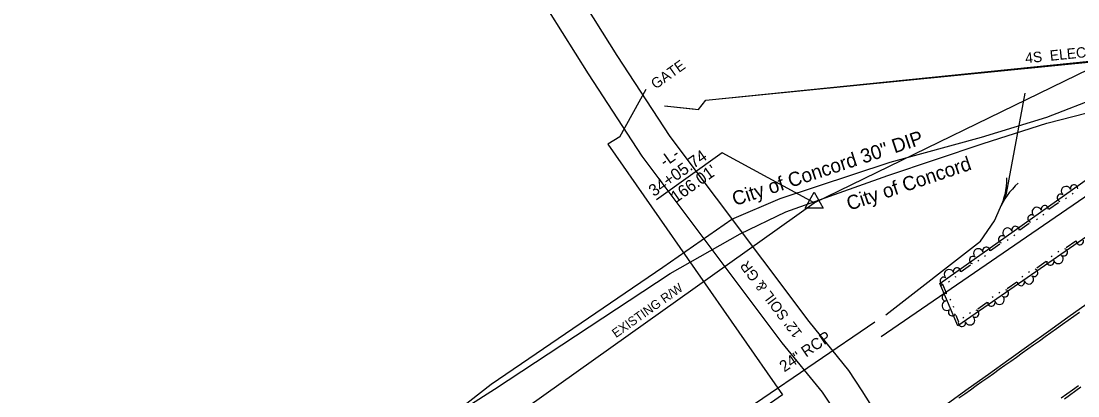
# Model space of a CAD drawing. Extents: x 1577032 to 1581865, y 611492 to 615011.
# Drawn here: x 1579793.8 to 1580168.3, y 613586.8 to 613719.5 of the extents above; entities that cross this region are included whole.
import ezdxf

# ---------------------------------------------------------------- set-up
doc = ezdxf.new("R2010")
doc.units = 0
for name, color, linetype in [('Exist Hydro Jurisdictional Stream or Body of Water', 7, 'Continuous'), ('Exist Hydro Stream Flow Arrow CELL', 7, 'Continuous'), ('Exist Other Culture Fence Line', 7, 'Continuous'), ('Exist Other Culture Fence Line Leader', 7, 'Continuous'), ('Exist Right of Way Line', 7, 'Continuous'), ('Exist Right of Way Line Text', 7, 'Continuous'), ('Exist Right of Way Monument CELL', 7, 'Continuous'), ('Exist Right of Way Monument Leader', 7, 'Continuous'), ('Exist Right of Way Monument Text', 7, 'Continuous'), ('Exist Roads EOP', 7, 'Continuous'), ('Exist Roads EOT', 7, 'Continuous'), ('Exist Structure Minor Pipes RCP 24 Inch', 7, 'Continuous'), ('Exist Structure Minor Pipes RCP 24 Inch Text', 7, 'Continuous'), ('Exist Utilities Telephone UG FO SUE LOS B', 7, 'Continuous'), ('Exist Utilities Telephone UG FO SUE LOS B Text', 7, 'Continuous'), ('Exist Utilities Water UG Line SUE LOS B', 7, 'Continuous'), ('Exist Utilities Water UG Line SUE LOS B Text', 7, 'Continuous'), ('Old_Level_11', 7, 'Continuous'), ('Old_Level_8', 7, 'Continuous'), ('Scratch_Level_4', 7, 'Continuous'), ('Scratch_Level_6', 7, 'Continuous')]:
    doc.layers.add(name, color=color, linetype=linetype)

msp = doc.modelspace()

# ---------------------------------------------------------------- linework, layer by layer
at = {"layer": 'Exist Hydro Jurisdictional Stream or Body of Water'}
msp.add_lwpolyline([(1580100.25, 613615.55), (1580133.87, 613641.64), (1580138.78, 613648.8), (1580143.1, 613658.51), (1580149.63, 613693.95)], dxfattribs=at)
at = {"layer": 'Exist Hydro Stream Flow Arrow CELL'}
msp.add_line((1580143.1, 613658.51), (1580143.1, 613658.51), dxfattribs=at)
for points in [[(1580143.06, 613664.01), (1580143.06, 613662.54), (1580142.9, 613661.05), (1580142.72, 613659.58), (1580142.43, 613658.17), (1580142.04, 613656.73), (1580141.58, 613655.31), (1580141.05, 613653.95)], [(1580147.23, 613662.13), (1580146.14, 613661.16), (1580145.13, 613660.05), (1580144.16, 613658.94), (1580143.29, 613657.78), (1580142.48, 613656.54), (1580141.72, 613655.25), (1580141.05, 613653.95)]]:
    msp.add_lwpolyline(points, dxfattribs=at)
at = {"layer": 'Exist Other Culture Fence Line'}
for p in [(1580036.43, 613691.58), (1580098.64, 613607.82)]:
    msp.add_line(p, (1580251.9, 613712.92), dxfattribs=at)
msp.add_lwpolyline([(1580021.78, 613689.53), (1580031.98, 613688.46)], dxfattribs=at)
at = {"layer": 'Exist Right of Way Line'}
for p, q in [((1580074.87, 613655.16), (1580329.14, 613778.75)), ((1579178.76, 613018.8), (1580074.87, 613655.16))]:
    msp.add_line(p, q, dxfattribs=at)
at = {"layer": 'Exist Right of Way Monument CELL'}
msp.add_line((1580074.87, 613655.16), (1580074.87, 613655.16), dxfattribs=at)
msp.add_lwpolyline([(1580071.63, 613653.27), (1580074.88, 613658.91), (1580078.12, 613653.27)], close=True, dxfattribs=at)
at = {"layer": 'Exist Right of Way Monument Leader'}
msp.add_lwpolyline([(1580074.87, 613655.16), (1580042.24, 613672.89), (1580018.97, 613656.24)], dxfattribs=at)
at = {"layer": 'Exist Roads EOP'}
for points in [[(1580171.59, 613619.36), (1580164.85, 613614.58), (1580157.96, 613609.65), (1580150.94, 613604.62), (1580143.84, 613599.55), (1580136.66, 613594.43), (1580129.41, 613589.25), (1580122.09, 613584.03)], [(1580163.65, 613585.82), (1580169.43, 613589.97)]]:
    msp.add_lwpolyline(points, dxfattribs=at)
at = {"layer": 'Exist Roads EOT'}
for points in [[(1580168.96, 613616.38), (1580166.92, 613614.93), (1580164.89, 613613.48), (1580162.85, 613612.04), (1580160.81, 613610.59), (1580158.78, 613609.14), (1580156.74, 613607.69), (1580154.71, 613606.24), (1580152.67, 613604.79), (1580150.63, 613603.35), (1580148.6, 613601.9), (1580146.56, 613600.45), (1580144.53, 613599), (1580142.49, 613597.55), (1580140.46, 613596.11), (1580138.42, 613594.66), (1580136.38, 613593.21), (1580134.35, 613591.76), (1580132.31, 613590.31), (1580130.28, 613588.86), (1580128.24, 613587.42), (1580126.21, 613585.97)], [(1580162.43, 613586.11), (1580164.46, 613587.56), (1580166.5, 613589), (1580168.54, 613590.45)]]:
    msp.add_lwpolyline(points, dxfattribs=at)
at = {"layer": 'Exist Structure Minor Pipes RCP 24 Inch'}
msp.add_line((1580054.05, 613584.23), (1580096.34, 613613.07), dxfattribs=at)
at = {"layer": 'Exist Utilities Telephone UG FO SUE LOS B'}
msp.add_lwpolyline([(1579762.43, 613445.5), (1579805.52, 613477.49), (1579874.3, 613528.42), (1579927.63, 613567.61), (1579961.57, 613589.13), (1580023.79, 613630.1), (1580048.6, 613644.24), (1580064.79, 613652.02), (1580101.01, 613664.86), (1580134.79, 613676.2), (1580157.3, 613683.34), (1580171.65, 613687.07), (1580205.63, 613699.27), (1580257.8, 613718.78), (1580277.93, 613732.3), (1580322.48, 613762.42), (1580357.71, 613789.14), (1580371.84, 613797.02), (1580398.85, 613808.57), (1580440.4, 613836.96), (1580497.32, 613877.42), (1580541.92, 613911.34), (1580565.99, 613928.5)], dxfattribs=at)
at = {"layer": 'Exist Utilities Water UG Line SUE LOS B'}
for p, q in [((1580157.33, 613685.56), (1580179.53, 613694.09)), ((1580134.18, 613678.38), (1580157.33, 613685.56)), ((1580101.85, 613669.53), (1580134.18, 613678.38)), ((1580062.81, 613656.66), (1580101.85, 613669.53)), ((1580045.74, 613649.33), (1580062.81, 613656.66)), ((1580021.22, 613632.44), (1580045.74, 613649.33)), ((1579960.34, 613590.95), (1580021.22, 613632.44)), ((1579928.88, 613566.57), (1579960.34, 613590.95))]:
    msp.add_line(p, q, dxfattribs=at)
at = {"layer": 'Old_Level_11'}
for points in [[(1580196.05, 613660.28), (1580125.81, 613611.65), (1580119.42, 613626.55), (1580178.67, 613668.56)], [(1580164.01, 613656.66), (1580164.35, 613656.89)], [(1580166.35, 613658.32), (1580166.69, 613658.55)], [(1580158.09, 613652.96), (1580161.43, 613655.33)], [(1580153.64, 613649.3), (1580153.98, 613649.54)], [(1580155.98, 613650.96), (1580156.32, 613651.2)], [(1580147.72, 613645.61), (1580151.06, 613647.98)], [(1580143.27, 613641.95), (1580143.6, 613642.19)], [(1580145.61, 613643.61), (1580145.95, 613643.85)], [(1580137.34, 613638.25), (1580140.69, 613640.62)], [(1580167.59, 613641.58), (1580164.22, 613639.24)], [(1580132.9, 613634.6), (1580133.23, 613634.83)], [(1580135.24, 613636.26), (1580135.57, 613636.5)], [(1580159.27, 613636.31), (1580158.93, 613636.08)], [(1580161.63, 613637.95), (1580161.29, 613637.71)], [(1580126.97, 613630.9), (1580130.32, 613633.27)], [(1580151.17, 613630.71), (1580150.84, 613630.48)], [(1580157.14, 613634.34), (1580153.77, 613632.01)], [(1580122.53, 613627.24), (1580122.86, 613627.48)], [(1580124.87, 613628.91), (1580125.2, 613629.14)], [(1580146.69, 613627.11), (1580143.32, 613624.77)], [(1580148.82, 613629.08), (1580148.48, 613628.84)], [(1580121.76, 613623.17), (1580120.43, 613626.26), (1580119.95, 613625.92)], [(1580140.72, 613623.47), (1580140.39, 613623.24)], [(1580123.27, 613620.69), (1580123.11, 613621.07)], [(1580136.24, 613619.87), (1580132.86, 613617.53)], [(1580138.36, 613621.84), (1580138.02, 613621.61)], [(1580124.4, 613618.05), (1580124.24, 613618.43)], [(1580130.27, 613616.24), (1580129.93, 613616)], [(1580126.17, 613612.9), (1580125.16, 613615.25)], [(1580127.91, 613614.6), (1580127.57, 613614.37)]]:
    msp.add_lwpolyline(points, dxfattribs=at)
for centre, radius, start, end in [((1580164.16, 613659.28), 1.69, 21.2995, 229.372), ((1580166.98, 613660.27), 1.3, 356.1042, 196.9008), ((1580162.3, 613656.95), 1.3, 53.7707, 254.5672), ((1580153.79, 613651.93), 1.69, 21.2995, 229.372), ((1580156.61, 613652.92), 1.3, 356.1042, 196.9008), ((1580151.93, 613649.6), 1.3, 53.7707, 254.5672), ((1580143.42, 613644.57), 1.69, 21.2995, 229.372), ((1580146.24, 613645.56), 1.3, 356.1042, 196.9008), ((1580141.55, 613642.24), 1.3, 53.7707, 254.5672), ((1580169.07, 613641.61), 1.3, 175.4659, 16.2625), ((1580133.05, 613637.22), 1.69, 21.2995, 229.372), ((1580135.87, 613638.21), 1.3, 356.1042, 196.9008), ((1580163.34, 613637.64), 1.3, 233.1324, 73.9289), ((1580131.18, 613634.89), 1.3, 53.7707, 254.5672), ((1580158.62, 613634.37), 1.3, 175.4659, 16.2625), ((1580161.45, 613635.33), 1.69, 200.6612, 48.7337), ((1580122.68, 613629.87), 1.69, 21.2995, 229.372), ((1580125.5, 613630.86), 1.3, 356.1042, 196.9008), ((1580152.89, 613630.4), 1.3, 233.1324, 73.9289), ((1580120.81, 613627.54), 1.3, 53.7707, 254.5672), ((1580148.17, 613627.13), 1.3, 175.4659, 16.2625), ((1580150.99, 613628.09), 1.69, 200.6612, 48.7337), ((1580142.43, 613623.16), 1.3, 233.1324, 73.9289), ((1580121.87, 613618.75), 1.69, 99.1909, 307.2634), ((1580121.49, 613621.71), 1.3, 73.9956, 274.7922), ((1580137.71, 613619.89), 1.3, 175.4659, 16.2625), ((1580140.54, 613620.85), 1.69, 200.6612, 48.7337), ((1580123.76, 613616.44), 1.3, 131.6621, 332.4587), ((1580131.98, 613615.93), 1.3, 233.1324, 73.9289), ((1580127.26, 613612.66), 1.3, 175.4659, 16.2625), ((1580130.09, 613613.62), 1.69, 200.6612, 48.7337)]:
    msp.add_arc(centre, radius, start, end, dxfattribs=at)
at = {"layer": 'Old_Level_8'}
for points in [[(1580021.78, 613689.53), (1580033.89, 613688.26), (1580036.43, 613691.58), (1580252.71, 613713.47)], [(1580005.94, 613678.54), (1580001.69, 613675.94), (1580063.69, 613587.13), (1579885.94, 613463.7), (1579781.84, 613393.87)]]:
    msp.add_lwpolyline(points, dxfattribs=at)
at = {"layer": 'Scratch_Level_4'}
for points in [[(1579958.98, 613780.55), (1580004.93, 613707.38), (1580023.71, 613678.63), (1580073.02, 613613.12), (1580087.1, 613595.85), (1580091.78, 613588.55)], [(1579948.7, 613774.09), (1579994.71, 613700.84), (1580013.77, 613671.65), (1580063.46, 613605.63), (1580077.7, 613588.18), (1580084.02, 613578.67)], [(1580091.78, 613588.55), (1580094.64, 613584.17), (1580098.2, 613580.79), (1580102.93, 613578.44), (1580106.87, 613577.66), (1580110.46, 613578.17), (1580114.26, 613580.13)]]:
    msp.add_lwpolyline(points, dxfattribs=at)
at = {"layer": 'Scratch_Level_6'}
msp.add_line((1580005.94, 613678.54), (1580015.36, 613695.36), dxfattribs=at)

# ---------------------------------------------------------------- texts
at = {"layer": 'Exist Other Culture Fence Line Leader'}
msp.add_text('4S  ELEC', height=3.691, rotation=5.7808, dxfattribs=at).set_placement((1580149.86, 613704.56))
at = {"layer": 'Exist Right of Way Line Text'}
msp.add_text('EXISTING R/W', height=3.2, rotation=35.38, dxfattribs=at).set_placement((1580004.63, 613607.24))
at = {"layer": 'Exist Right of Way Monument Text'}
for s, p in [('34+05.74', (1580018.05, 613657.19)), ('-L-', (1580021.94, 613667.66)), ("166.01'", (1580025.85, 613654.99))]:
    msp.add_text(s, height=4.2, rotation=35.2934, dxfattribs=at).set_placement(p)
at = {"layer": 'Exist Structure Minor Pipes RCP 24 Inch Text'}
msp.add_text('24" RCP', height=4, rotation=34.299, dxfattribs=at).set_placement((1580064.28, 613595.08))
at = {"layer": 'Exist Utilities Telephone UG FO SUE LOS B Text'}
msp.add_text('City of Concord', height=5, rotation=18.561, dxfattribs=at).set_placement((1580087.34, 613652.36))
at = {"layer": 'Exist Utilities Water UG Line SUE LOS B Text'}
msp.add_text('City of Concord 30" DIP', height=5, rotation=18.2399, dxfattribs=at).set_placement((1580046.76, 613654))
at = {"layer": 'Scratch_Level_4'}
msp.add_text("12' SOIL & GR", height=3.6909, rotation=126.9682, dxfattribs=at).set_placement((1580070.79, 613609.08))
at = {"layer": 'Scratch_Level_6'}
msp.add_text('GATE', height=3.691, rotation=35.38, dxfattribs=at).set_placement((1580018.67, 613695.26))

doc.saveas('drawing.dxf')
